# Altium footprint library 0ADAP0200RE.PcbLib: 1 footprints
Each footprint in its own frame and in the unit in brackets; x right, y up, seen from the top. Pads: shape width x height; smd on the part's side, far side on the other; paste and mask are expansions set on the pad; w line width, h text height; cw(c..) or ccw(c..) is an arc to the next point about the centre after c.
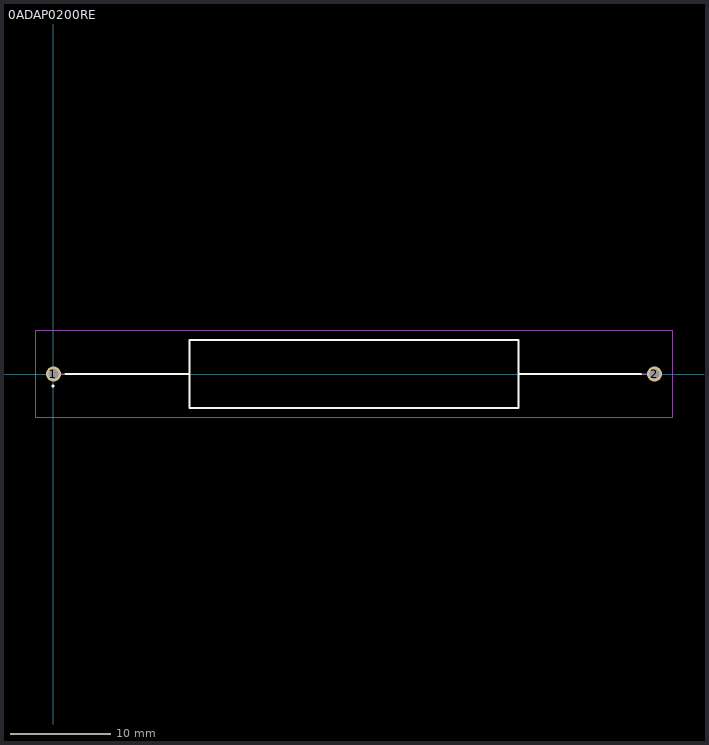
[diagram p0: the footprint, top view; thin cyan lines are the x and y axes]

## 0ADAP0200RE [mm]
pads (2):
  round 1.515 hole 1.01: 1(0,0) 2(59.84,0)
Top Overlay:
  lines w0.2: 1.2,0 13.5,0 ; 46.32,0 58.5,0 ; -0.1,-1.2 -0.1,-1.2 ; -0.1,-1.2 ccw(c-0.05,-1.2) 0,-1.2 ; -0.1,-1.2 cw(c-0.05,-1.2) 0,-1.2 ; -0.1,-1.2 -0.1,-1.2 ; -0.1,-1.2 ccw(c-0.05,-1.2) 0,-1.2 ; 0,-1.2 0,-1.2 ; 13.52,-3.38 46.32,-3.38 46.32,3.38 13.52,3.38 13.52,-3.38
Mechanical 15:
  lines w0.1: 0,0 13.52,0 ; 0,0 13.52,0 ; 0,0 0,0 ; 13.52,0 13.52,0 ; 46.32,0 59.84,0 ; 46.32,0 46.32,0 ; 46.32,0 59.84,0 ; 59.84,0 59.84,0 ; 13.52,-3.38 46.32,-3.38 46.32,3.38 13.52,3.38 13.52,-3.38
Mechanical 20:
  lines w0.1: -1.758,-4.38 61.598,-4.38 61.598,4.38 -1.758,4.38 -1.758,-4.38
